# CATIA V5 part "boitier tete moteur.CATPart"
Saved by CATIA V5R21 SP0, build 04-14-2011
Part number: boitier tete moteur
Material "Aluminium": density 2710 kg/m3, Young's modulus 7e+10 Pa, Poisson ratio 0.346, thermal expansion 2.36e-05 1/K
Bounding box of the stored display mesh (mm): x -15.717 to 15.717, y 0 to 14, z -15.717 to 15.717
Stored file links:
  C:\Users\Utilisateur\Desktop\Fichiers à télécharger dans l'ouvrage\Exercice 9 Pompe de ventilation.CATDrawing (corrigé)\boitier tete moteur.CATPart
  C:\Program Files\Dassault Systemes\B21\win_b64\startup\materials\French\Catalog.CATMaterial
  C:\Users\Utilisateur\Desktop\Fichiers à télécharger dans l'ouvrage\Exercice 9 Pompe de ventilation.CATDrawing (corrigé)\CATIA_EnvironmentMap_DSBlack_512x512.jpg
  C:\Users\Olivier\Desktop\redaction CATIA (local)\pompe à moteur de ventilation refait\Pompe_a_moteur_de_ventilation.CATProduct
  C:\Users\Olivier\Desktop\redaction CATIA (local)\pompe à moteur de ventilation refait\Ecrou a collerette M5.CATPart
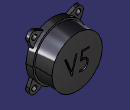
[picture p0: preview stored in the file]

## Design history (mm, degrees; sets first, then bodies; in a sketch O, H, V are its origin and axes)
Body1 (main body), material "Aluminium"
  Sketch1 on zx-plane, origin (0, 0, 0), H (-1, 0, 0), V (0, 0, 1)
    circle A1 centre (0, 0) radius 15.5
    circle A2 centre (0, 0) radius 14.5
    radius A2 = 14.5
  MultiPad1: profile Sketch1, domains (length 14; length 4)
  Sketch2 on face of MultiPad1, origin (0, 0, 0), H (1, 0, 0), V (0, 0, 1)
    circle A1 centre (0, 0) radius 11.5
  Pocket1: profile Sketch2, direction (0, 1, 0), length 12
  Sketch3 on face of MultiPad1, origin (0, 0, 0), H (1, 0, 0), V (0, 0, 1)
    projected circle E1 centre (0, 0) radius 15.5 from edge [face of MultiPad1 | face of MultiPad1 from Sketch1.A1]
    projected arc E2 centre (0, 0) radius 15.5 from (-7.465, 13.5839) to (-13.5839, 7.465) ccw from edge [face of MultiPad1 | face of MultiPad1 from Sketch1.A1]
    projected arc E3 centre (0, 0) radius 15.5 from (-13.5839, -7.465) to (-7.465, -13.5839) ccw from edge [face of MultiPad1 | face of MultiPad1 from Sketch1.A1]
    projected arc E4 centre (0, 0) radius 15.5 from (7.465, -13.5839) to (13.5839, -7.465) ccw from edge [face of MultiPad1 | face of MultiPad1 from Sketch1.A1]
    projected arc E5 centre (0, 0) radius 15.5 from (13.5839, 7.465) to (7.465, 13.5839) ccw from edge [face of MultiPad1 | face of MultiPad1 from Sketch1.A1]
    circle A1 centre (12.7279, 12.7279) radius 1.5
    point P1 (12.7279, 12.7279)
    arc A2 centre (12.7279, 12.7279) radius 3 from (15.4468, 11.4601) to (11.4601, 15.4468) ccw
    line L1 (15.4468, 11.4601) -> (13.5839, 7.465)
    point P2 (15.4468, 11.4601)
    point P3 (11.4601, 15.4468)
    line L2 (11.4601, 15.4468) -> (7.465, 13.5839)
    point P4 (7.465, 13.5839)
    point P5 (13.5839, 7.465)
    point P7 (-15.4468, 11.4601)
    point P8 (-11.4601, 15.4468)
    point P9 (-7.465, 13.5839)
    point P10 (-13.5839, 7.465)
    circle A3 centre (-12.7279, 12.7279) radius 1.5
    arc A4 centre (-12.7279, 12.7279) radius 3 from (-15.4468, 11.4601) to (-11.4601, 15.4468) cw
    line L3 (-15.4468, 11.4601) -> (-13.5839, 7.465)
    line L4 (-11.4601, 15.4468) -> (-7.465, 13.5839)
    point P12 (15.4468, -11.4601)
    point P13 (11.4601, -15.4468)
    point P14 (7.465, -13.5839)
    point P15 (13.5839, -7.465)
    point P17 (-15.4468, -11.4601)
    point P18 (-11.4601, -15.4468)
    point P19 (-7.465, -13.5839)
    point P20 (-13.5839, -7.465)
    circle A5 centre (12.7279, -12.7279) radius 1.5
    arc A6 centre (12.7279, -12.7279) radius 3 from (15.4468, -11.4601) to (11.4601, -15.4468) cw
    line L5 (15.4468, -11.4601) -> (13.5839, -7.465)
    line L6 (11.4601, -15.4468) -> (7.465, -13.5839)
    circle A7 centre (-12.7279, -12.7279) radius 1.5
    arc A8 centre (-12.7279, -12.7279) radius 3 from (-15.4468, -11.4601) to (-11.4601, -15.4468) ccw
    line L7 (-15.4468, -11.4601) -> (-13.5839, -7.465)
    line L8 (-11.4601, -15.4468) -> (-7.465, -13.5839)
    distance P1 O = 18
    radius A2 = 3
    tangency: A2 L1
    coincidence: E1 P4, E1 P5
    symmetry: P2 P7 V, P3 P8 V, P4 P9 V, P5 P10 V, A1 A3 V, A2 A4 V, L1 L3 V, L2 L4 V, P2 P12 H, P3 P13 H, P4 P14 H, P5 P15 H, P7 P17 H, P8 P18 H, P9 P19 H, P10 P20 H, A1 A5 H, A2 A6 H, L1 L5 H, L2 L6 H, A3 A7 H, A4 A8 H, L3 L7 H, L4 L8 H
  Pad1: profile Sketch3, direction (0, 1, 0), length 2
  Sketch4 on face of MultiPad1, origin (0, 14, 0), H (-1, 0, 0), V (0, 0, 1)
    line L1 (-7.2074, 4.3533) -> (-3.0577, -5.6747)
    point P2 (-3.0577, -5.6747)
    point P3 (-3.0577, -5.6747)
    point P4 (0.0056, 4.3533)
    line L2 (0.0056, 4.3533) -> (-3.0577, -5.6747)
    line L3 (-7.2074, 4.3533) -> (-6.1898, 4.3533)
    line L4 (-6.1898, 4.3533) -> (-3.0677, -3.1914)
    line L5 (-3.0677, -3.1914) -> (-0.7629, 4.3533)
    point P7 (-0.7629, 4.3533)
    line L6 (-0.7629, 4.3533) -> (0.0056, 4.3533)
    point P8 (0.0056, 4.3533)
    point P9 (2.7205, 4.3533)
    line L7 (2.7205, 4.3533) -> (2.0273, -0.6137)
    line L8 (2.7205, 4.3533) -> (7.0034, 4.3533)
    line L9 (7.0034, 4.3533) -> (6.8938, 3.5681)
    line L10 (6.8938, 3.5681) -> (3.3501, 3.5681)
    line L11 (3.3501, 3.5681) -> (2.8903, 0.2738)
    point P14 (2.8903, 0.2738)
    spline S1 through (2.8903, 0.2738) (6.1305, -1.2523) (5.8312, -4.3043) (1.3117, -5.7405)
    offsetcurve C1
    construction line L12 (2.8903, 0.2738) -> (2.9402, -0.6249)
    point P17 (2.8903, 0.2738)
    construction line L13 through (2.8903, 0.2738) direction (-0.9985, -0.0554)
    construction line L14 (1.3117, -5.7405) -> (1.5746, -4.8798)
    point P18 (1.3117, -5.7405)
    construction line L15 through (1.1611, -5.6945) direction (-0.9564, 0.2922)
    line L16 (2.9402, -0.6249) -> (2.0273, -0.6137)
    line L17 (1.5746, -4.8798) -> (1.3117, -5.7405)
    point P19 (1.3117, -5.7405)
    point P20 (2.8903, 0.2738)
    point P21 (1.3117, -5.7405)
    horizontal: L3 H, L6 H, L8 H, L10 H
    parallelism: L4 L1, L5 L2, L9 L7, L11 L7, L17 L2
    coincidence: P7 L3, P8 L2, P9 L6, P20 P14, P21 L7, P20 P17, P21 P18, P4 P8, P19 P21, P2 P3
    tangency: L13 S1, L15 S1
    perpendicularity: L12 L13, L14 L15
  Pocket2: profile Sketch4, direction (0, -1, 0), length 1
